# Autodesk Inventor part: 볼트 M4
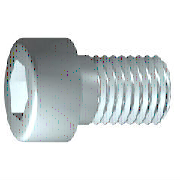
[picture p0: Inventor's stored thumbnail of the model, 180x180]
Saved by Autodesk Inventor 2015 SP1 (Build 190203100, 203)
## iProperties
IsCustomPart: 0
Created: 2012-02
Part Number: 볼트 M4
Material: 스테인리스강
Description: 6각 소켓 머리 캡 나사
Document SubType Name: Modeling
Standard: ISO 4762
Designer: mduedu
Standard Revision: Fourth edition 2004-03-01
Standards Organization: ISO
Language: ko-KR
Size Designation: M4 x 12
Categories: <MemberInstance><Categories><Category DisplayName="조임쇠" InternalName="e4da775c-781d-43d5-af7c-5136215cf5a6" Mnemonic="FSTN"><Category DisplayName="볼트" InternalN
Density: 8.08 g/cm^3
Appearance: 반광택
Author: mduedu
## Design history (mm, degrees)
sketch "스케치1"
  geometry: L1 (-1, 0)-(12, 0); L2 (12, 0)-(12, 2); L3 (12, 2)-(1.75, 2); L4 (1.75, 2)-(1.32, 2); L5 (1.32, 2)-(0, 2); L6 (0, 2)-(0, 3.5); L7 (0, 3.5)-(-4, 3.5); L8 (-4, 3.5)-(-4, 1.732); L9 (-4, 1.732)-(-2, 1.732); L10 (-2, 1.732)-(-1, 0); L11 (-7.2, 0)-(15.2, 0) reference; L12 (0, -0.7)-(0, 4.2) reference; L13 (1.75, 2)-(0, 2)
  constraints: 22 end point, 6 parallel, 2 collinear, 2 perpendicular, 1 horizontal, 1 point on line
  dimensions: "d1" = 10.25 distance from line of L3.end L2 (= GEL); "d2" = 0.42952 distance of L4.end L3.end (computed from GAL); "d3" = 4 distance between parallel lines of L8 L6 (= KOH); "d4" = 2 distance of L8.end L9.end (= INTI); "d5" = 60 deg angle of L10 L1; "d6" = 4 diameter of L3 L1 (= GD); "d7" = 4 diameter of L5 L1 (= BDM); "d8" = 3.4641 diameter of L9 L1 (= 1.1547 x SW); "d9" = 7 diameter of L7 L1 (= KOD); "d26" = 12 distance between parallel lines of L12 L2 (= NLG)
revolve "본체" sketch "스케치1" stored, may be unused: angle "d10" = 90 deg
sketch "스케치2"
  geometry: L1 (0, -4.9)-(0, 4.9) reference; L2 (-4.9, 0)-(4.9, 0) reference; L3 (1.732, 0)-(0.866, -1.5); L4 (0.866, -1.5)-(-0.866, -1.5); L5 (-0.866, -1.5)-(-1.732, 0); L6 (-1.732, 0)-(-0.866, 1.5); L7 (-0.866, 1.5)-(0.866, 1.5); L8 (0.866, 1.5)-(1.732, 0); 2 further points
  constraints: 12 end point, 1 coincident, 1 horizontal alignment, 1 point on line, 12 other
extrude "슬롯" join sketch "스케치2" stored distance "d11" = 10; taper "d12" = 0 deg
workplane "Work Plane1"
fillet "Fillet2" dims "d30" = 0.1 (= R)
body "Solid1"
fillet "모깎기1" dims "d17" = 0.4 (= RR)
feature "스레드" dims "d13" = 10.25 (= GEL), "d14" = 0
chamfer "모따기1" distance "d15" = 0.42941 (= -0.5 x SPD + 0.5 x GD); stored, may be unused: second distance "d16" = 0.42941 (= GUL), angle "d27" = 45 deg
other parameters: "GD" = 4 [user parameter; used in 2 equation terms], "NLG" = 12 [user parameter; used in 1 equation term], "GEL" = 10.25 [user parameter; used in 2 equation terms], "KOD" = 7 [user parameter; used in 1 equation term], "KOH" = 4 [user parameter; used in 1 equation term], "INTI" = 2 [user parameter; used in 1 equation term], "GAL" = 0.42941 (= 0.61345 x PTC) [user parameter; used in 1 equation term], "GUL" = 0.42941 (= 0.61345 x PTC) [user parameter; used in 1 equation term], "BDM" = 4 (= NND) [user parameter; used in 1 equation term], "SW" = 3 [user parameter; used in 2 equation terms], "RR" = 0.4 [user parameter; used in 1 equation term], "SPD" = 3.14117 (= NND - 1.2269 x PTC) [user parameter; used in 1 equation term], "d19" = 0, "d28" = 0, "d29" = 0, "R" = 0.1 [user parameter; used in 1 equation term], "TOA" = 30 deg [user parameter], "GD1" = 3.14117 (= THREADDIA - 1.2269 x PTC) [user parameter], "THREADDIA" = 4 [user parameter; used in 1 equation term], "FAWI" = 45 deg [user parameter], "TPU" = 14.28571 (computed from PTC) [user parameter], "PTC" = 0.7 [user parameter; used in 5 equation terms], "NND" = 4 [user parameter; used in 2 equation terms], "E0" = 3.465 (= 1.155 x SW) [user parameter]
